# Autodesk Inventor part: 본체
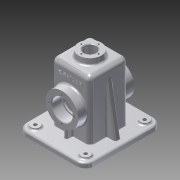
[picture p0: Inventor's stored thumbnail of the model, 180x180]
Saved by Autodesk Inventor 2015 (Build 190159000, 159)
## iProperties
Created: 2016-02
Part Number: 본체
Material: 알루미늄 6061
Document SubType Name: Modeling
Designer: Administrator
Density: 2.7 g/cm^3
Appearance: 알루미늄 - 평지
Mass: 801.79 g
Surface Area: 906.477 cm^2
Volume: 296.959 cm^3
Author: Administrator
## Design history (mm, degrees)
sketch "스케치1"
  geometry: L1 (-42.5, 65)-(42.5, 65); L2 (57.5, 50)-(57.5, -50); L3 (42.5, -65)-(-42.5, -65); L4 (-57.5, -50)-(-57.5, 50); L5 (-57.5, 65)-(57.5, -65); L6 (57.5, 65)-(-57.5, -65); A1 r 15 centre (-42.5, 50) between (-42.5, 65) and (-57.5, 50); A2 r 15 centre (-42.5, -50) between (-57.5, -50) and (-42.5, -65); A3 r 15 centre (42.5, -50) between (42.5, -65) and (57.5, -50); A4 r 15 centre (42.5, 50) between (57.5, 50) and (42.5, 65); 1 further point
  constraints: 12 end point, 8 point on circle, 8 point on line, 8 tangent, 4 centre point, 3 equal radius, 2 midpoint, 2 parallel, 1 horizontal, 1 perpendicular
  dimensions: "d0" = 130 distance of L6.start L5.end; "d1" = 115 distance of L5.start L6.start; "d2" = 15 radius of A1
extrude "돌출1" new body sketch "스케치1" distance "d3" = 10; taper "d4" = 0 deg
sketch "스케치2"
  geometry: C1 r 7.5 at (-42.5, 50); C2 r 7.5 at (42.5, 50); C3 r 7.5 at (42.5, -50); C4 r 7.5 at (-42.5, -50); A1 r 15 centre (-42.5, -50) between (-57.5, -50) and (-42.5, -65) reference; A2 r 15 centre (42.5, -50) between (42.5, -65) and (57.5, -50) reference; A3 r 15 centre (42.5, 50) between (57.5, 50) and (42.5, 65) reference; A4 r 15 centre (-42.5, 50) between (-42.5, 65) and (-57.5, 50) reference; 1 further point
  constraints: 4 centre point, 4 coincident
  dimensions: "d5" = 15 diameter of C1; "d6" = 15 diameter of C2 (= d5); "d7" = 15 diameter of C3 (= d6); "d8" = 15 diameter of C4 (= d5)
extrude "돌출2" join sketch "스케치2" distance "d9" = 3; taper "d10" = 0 deg
sketch "스케치3"
  geometry: L1 (57.5, 50)-(57.5, -50) reference; L2 (-42.5, 65)-(42.5, 65) reference; L3 (-57.5, -50)-(-57.5, 50) reference; L4 (42.5, -65)-(-42.5, -65) reference; L5 (-52.5, -50)-(-52.5, 50); L6 (-42.5, 60)-(42.5, 60); L7 (52.5, 50)-(52.5, -50); L8 (42.5, -60)-(-42.5, -60); L9 (-57.5, -50)-(-57.5, 50); L10 (-42.5, 65)-(42.5, 65); L11 (57.5, 50)-(57.5, -50); L12 (42.5, -65)-(-42.5, -65); A1 r 15 centre (42.5, 50) between (57.5, 50) and (42.5, 65) reference; A2 r 15 centre (-42.5, 50) between (-42.5, 65) and (-57.5, 50) reference; A3 r 15 centre (-42.5, -50) between (-57.5, -50) and (-42.5, -65) reference; A4 r 15 centre (42.5, -50) between (42.5, -65) and (57.5, -50) reference; A5 r 10 centre (-42.5, -50) between (-52.5, -50) and (-42.5, -60); A6 r 10 centre (-42.5, 50) between (-42.5, 60) and (-52.5, 50); A7 r 10 centre (42.5, 50) between (52.5, 50) and (42.5, 60); A8 r 10 centre (42.5, -50) between (42.5, -60) and (52.5, -50); A9 r 15 centre (-42.5, -50) between (-57.5, -50) and (-42.5, -65); A10 r 15 centre (-42.5, 50) between (-42.5, 65) and (-57.5, 50); A11 r 15 centre (42.5, 50) between (57.5, 50) and (42.5, 65); A12 r 15 centre (42.5, -50) between (42.5, -65) and (57.5, -50); 1 further point
  constraints: 16 end point, 16 point on circle, 8 centre point, 14 other
  dimensions: "d11" = 5 distance between parallel lines of L4 L8; "d12" = 0 distance between parallel lines of L4 L12
extrude "돌출3" cut sketch "스케치3" distance "d13" = 2; taper "d14" = 0 deg
sketch "스케치5"
  geometry: L1 (-42.5, 0)-(42.5, 0) reference; C1 r 27.5 at (0, 55); C2 r 15 at (0, 55); 2 further points
  constraints: 2 centre point, 1 coincident, 1 midpoint, 1 vertical alignment
  dimensions: "d17" = 55 diameter of C1; "d18" = 55 distance from line of L1 C1.centre; "d19" = 30 diameter of C2
extrude "돌출4" join sketch "스케치5" stored distance "d20" = 95; taper "d21" = 0 deg
sketch "스케치6"
  geometry: L1 (-24.5, 32.5)-(24.5, 32.5); L2 (32.5, 24.5)-(32.5, -24.5); L3 (24.5, -32.5)-(-24.5, -32.5); L4 (-32.5, -24.5)-(-32.5, 24.5); L5 (-32.5, 32.5)-(32.5, -32.5); L6 (32.5, 32.5)-(-32.5, -32.5); A1 r 8 centre (-24.5, 24.5) between (-24.5, 32.5) and (-32.5, 24.5); A2 r 8 centre (-24.5, -24.5) between (-32.5, -24.5) and (-24.5, -32.5); A3 r 8 centre (24.5, -24.5) between (24.5, -32.5) and (32.5, -24.5); A4 r 8 centre (24.5, 24.5) between (32.5, 24.5) and (24.5, 32.5); 3 further points
  constraints: 12 end point, 8 point on circle, 8 point on line, 8 tangent, 4 centre point, 4 midpoint, 3 equal radius, 2 parallel, 1 horizontal, 1 perpendicular
  dimensions: "d22" = 65 distance of L6.start L5.end; "d23" = 65 distance of L5.start L6.start; "d47" = 8 radius of A1
extrude "돌출5" join sketch "스케치6" distance "d28" = 100; taper "d29" = 0 deg
sketch "스케치7"
  geometry: L1 (24.5, -32.5)-(-24.5, -32.5) reference; L2 (-24.5, 32.5)-(24.5, 32.5) reference; L3 (-3, -22.5)-(3, -22.5); L4 (3, -22.5)-(3, -42.5); L5 (3, -42.5)-(-3, -42.5); L6 (-3, -42.5)-(-3, -22.5); L7 (-3, -22.5)-(3, -42.5); L8 (3, -22.5)-(-3, -42.5); L9 (-3, 42.5)-(3, 42.5); L10 (3, 42.5)-(3, 22.5); L11 (3, 22.5)-(-3, 22.5); L12 (-3, 22.5)-(-3, 42.5); L13 (-3, 42.5)-(3, 22.5); L14 (3, 42.5)-(-3, 22.5); 7 further points
  constraints: 24 end point, 6 midpoint, 4 parallel, 2 horizontal, 2 perpendicular
  dimensions: "d30" = 10 distance between parallel lines of L5 L1; "d31" = 6 distance of L4.end L5.end; "d32" = 10 distance between parallel lines of L2 L9; "d33" = 6 distance of L9.start L9.end
extrude "돌출6" join sketch "스케치7" stored distance "d34" = 100; taper "d35" = 0 deg
sketch "스케치9"
  geometry: C1 r 20 at (0, 0); 1 further point
  constraints: 1 centre point, 1 coincident
  dimensions: "d37" = 40 diameter of C1
extrude "돌출7" join sketch "스케치9" distance "d38" = 10; taper "d39" = -5 deg
sketch "스케치11"
  geometry: L1 (27.5, -27.5)-(-27.5, -27.5); L2 (-27.5, -27.5)-(-27.5, 27.5); L3 (-27.5, 27.5)-(27.5, 27.5); L4 (27.5, 27.5)-(27.5, -27.5); L5 (27.5, -27.5)-(-27.5, 27.5); L6 (-27.5, -27.5)-(27.5, 27.5); 1 further point
  constraints: 12 end point, 2 midpoint, 2 parallel, 1 horizontal, 1 perpendicular
  dimensions: "d40" = 55 distance of L1.start L1.end; "d41" = 55 distance of L1.end L2.end
extrude "돌출8" cut sketch "스케치11" distance "d42" = 105; taper "d43" = 0 deg
sketch "스케치12"
  geometry: C1 r 19.125 at (0, 0) reference; C2 r 10.5 at (0, 0)
  constraints: 1 centre point, 1 coincident
  dimensions: "d44" = 21 diameter of C2
extrude "돌출9" cut sketch "스케치12" stored distance "d45" = 105; taper "d46" = 0 deg
sketch "스케치14"
  geometry: L1 (-32.5, 10)-(-32.5, 110) reference; L2 (-32.5, 95.069)-(-47.5, 10); L3 (-47.5, 10)-(-32.5, 10); L4 (-50, 10)-(-35, 10) reference; L5 (-32.5, 10)-(-32.5, 95.069); L6 (-57.5, 2)-(-57.5, 10) reference; L7 (32.5, 10)-(32.5, 110) reference; L8 (32.5, 95.069)-(32.5, 10); L9 (32.5, 10)-(47.5, 10); L10 (35, 10)-(50, 10) reference; L11 (47.5, 10)-(32.5, 95.069); L12 (57.5, 2)-(57.5, 10) reference; 1 further point
  constraints: 12 end point, 3 collinear, 3 point on line
  dimensions: "d51" = 10 distance from line of L6 L2.end; "d52" = 10 deg angle of L6 L2; "d53" = 10 distance from line of L9.end L12; "d54" = 10 deg angle of L12 L11
extrude "돌출10" join sketch "스케치14" stored distance "d55" = 10; taper "d56" = 0 deg
sketch "스케치15"
  geometry: C1 r 15 at (0, 0) reference; C2 r 15 at (0, 0); 1 further point
  constraints: 1 centre point, 1 coincident, 1 concentric
extrude "돌출11" cut sketch "스케치15" stored distance "d57" = 6; taper "d58" = 0 deg
sketch "스케치16"
  geometry: C1 r 15 at (0, 0) reference; C2 r 27.5 at (0, 0) reference; C3 r 17.5 at (0, 0); 1 further point
  constraints: 1 centre point, 1 coincident
  dimensions: "d59" = 35 diameter of C3
extrude "돌출12" cut sketch "스케치16" distance "d60" = 17; taper "d61" = 0 deg
sketch "스케치17"
  geometry: C1 r 15 at (0, 0) reference; C2 r 27.5 at (0, 0) reference; C3 r 17.5 at (0, 0); 1 further point
  constraints: 1 centre point, 1 coincident
  dimensions: "d62" = 35 diameter of C3
extrude "돌출13" cut sketch "스케치17" distance "d63" = 17; taper "d64" = 0 deg
fillet "모깎기1" dims "d65" = 3
fillet "모깎기2" dims "d66" = 3
fillet "모깎기3" dims "d67" = 3
fillet "모깎기4" dims "d68" = 1
fillet "모깎기5" dims "d69" = 3
fillet "모깎기6" dims "d70" = 3
chamfer "모따기1" distance "d71" = 1; stored, may be unused: second distance "d72" = 2, angle "d73" = 45 deg
fillet "모깎기7" dims "d74" = 3
fillet "모깎기8" dims "d75" = 3
fillet "모깎기9" dims "d76" = 8
fillet "모깎기10" dims "d77" = 3
node "작업 평면1"
sketch "스케치19"
  geometry: L1 (-19.125, 65)-(19.125, 65) reference; 2 further points
  constraints: 1 vertical alignment, 1 other
  dimensions: "d80" = 26 distance from line of L1 point (0, 39)
feature "엠보싱1" sketch "스케치19" dims "d81" = 0.5, "d82" = 0
hole "구멍1" diameter "d85" = 6; stored, may be unused: countersink angle "d89" = 90 deg, drill point angle "d91" = 118 deg; dims "d86" = 6, "d87" = 4, "d88" = 2, "d90" = 8, "d110" = 10, "d111" = 10
hole "구멍2" diameter "d94" = 6; stored, may be unused: countersink angle "d98" = 90 deg, drill point angle "d100" = 118 deg; dims "d95" = 6, "d96" = 4, "d97" = 2, "d99" = 8, "d112" = 10, "d113" = 10
hole "구멍3" diameter "d103" = 6; stored, may be unused: countersink angle "d107" = 90 deg, drill point angle "d109" = 118 deg; dims "d101" = 10, "d102" = 10, "d104" = 6, "d105" = 4, "d106" = 2, "d108" = 8
hole "구멍4" diameter "d116" = 6; stored, may be unused: countersink angle "d120" = 90 deg, drill point angle "d122" = 118 deg; dims "d114" = 10, "d115" = 10, "d117" = 6, "d118" = 4, "d119" = 2, "d121" = 8
sketch "스케치20"
  geometry: C1 r 27.5 at (0, 0) reference; 2 further points
  constraints: 1 vertical alignment
  dimensions: "d123" = 21 distance of C1.centre point (0, 21)
hole "구멍5" sketch "스케치20" at (0, 21) diameter "d124" = 3.242; stored, may be unused: countersink angle "d128" = 90 deg, drill point angle "d130" = 118 deg; dims "d125" = 8, "d126" = 4, "d127" = 2, "d129" = 10
sketch "스케치21"
  geometry: L1 (-42.5, 55)-(42.5, 55) reference; C1 r 27.5 at (0, 0) reference; 3 further points
  constraints: 1 midpoint, 1 vertical alignment
  dimensions: "d134" = 21 distance of C1.centre point (0, -21)
hole "구멍6" sketch "스케치21" at (0, -21) diameter "d135" = 3.242; stored, may be unused: countersink angle "d139" = 90 deg, drill point angle "d141" = 118 deg; dims "d136" = 8, "d137" = 4, "d138" = 2, "d140" = 10
sketch "스케치22"
  geometry: C1 r 19.125 at (0, 0) reference; 1 further point
  constraints: 1 horizontal alignment
  dimensions: "d145" = 14.5 distance of C1.centre point (-14.5, 0)
hole "구멍7" sketch "스케치22" at (-14.5, 0) diameter "d146" = 2.459; stored, may be unused: countersink angle "d150" = 90 deg, drill point angle "d152" = 118 deg; dims "d147" = 7, "d148" = 4, "d149" = 2, "d151" = 9
fillet "모깎기11" dims "d156" = 0.3
fillet "모깎기12" dims "d157" = 3
node "솔리드1"
pattern_circular "원형 패턴1" dims angle "d132" = 360 deg
pattern_circular "원형 패턴2" dims angle "d143" = 360 deg
pattern_circular "원형 패턴3" dims angle "d154" = 360 deg
other parameters: "d79" = 62
